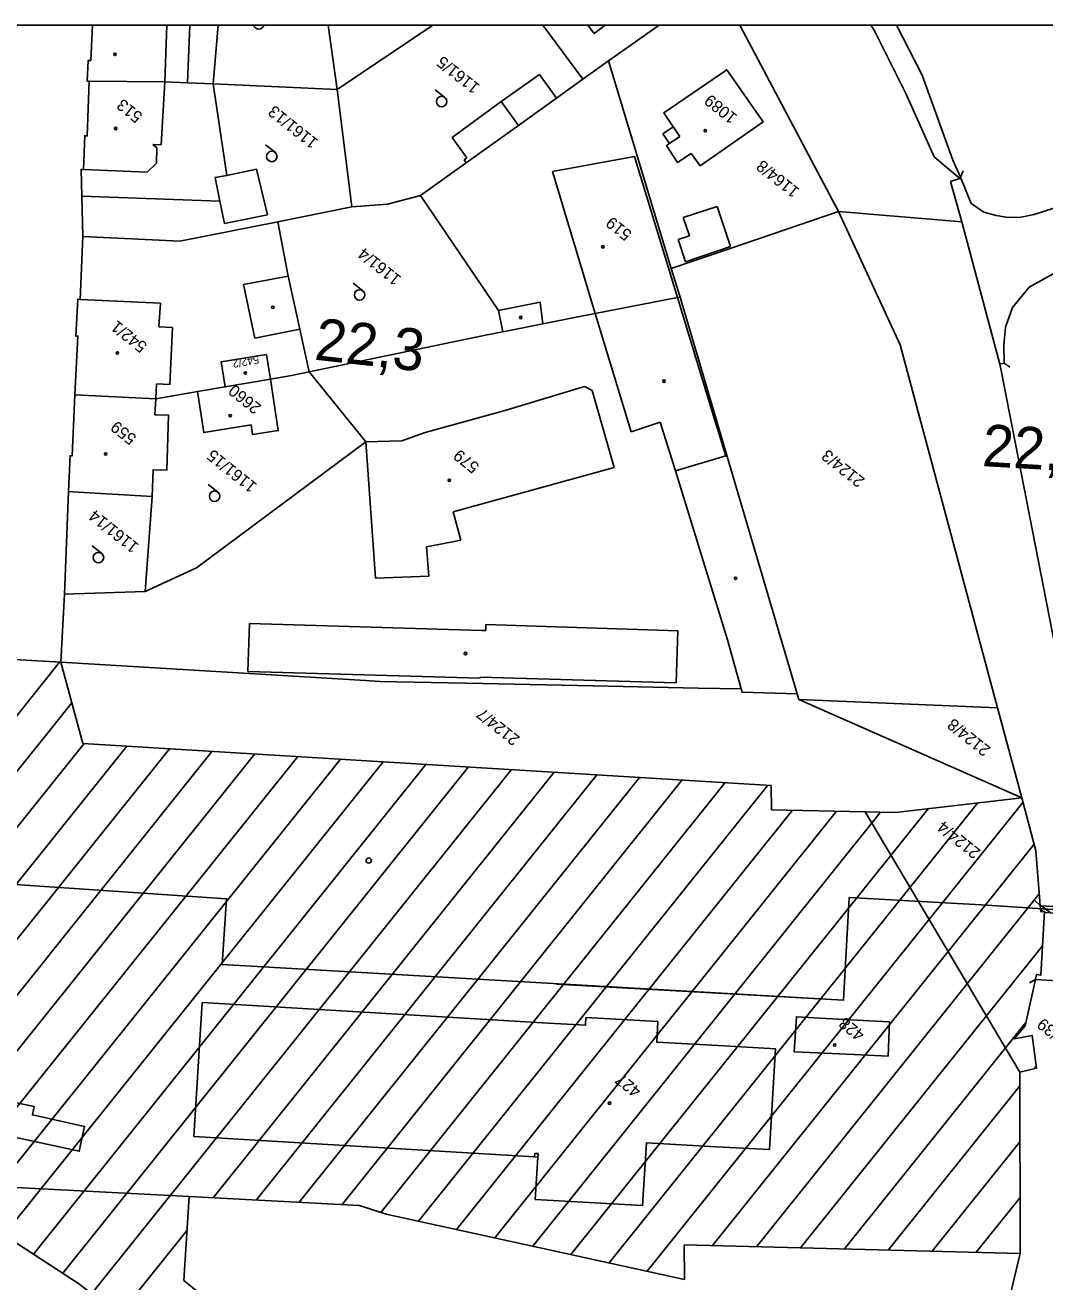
# Model space of a CAD drawing. Extents: x -794765 to -785424, y -1118958 to -1108731.
# Drawn here: x -794413.8 to -794268, y -1110211 to -1110031.4 of the extents above; entities that cross this region are included whole.
import ezdxf

# ---------------------------------------------------------------- set-up
doc = ezdxf.new("R2010")
doc.units = 0
for name, color, linetype in [('Level 66', 7, 'Continuous'), ('Level 71', 7, 'Continuous'), ('Level 73', 7, 'Continuous'), ('Level 75', 7, 'Continuous'), ('Level 76', 7, 'Continuous'), ('Level 77', 7, 'Continuous'), ('Level 78', 7, 'Continuous'), ('Level 79', 7, 'Continuous'), ('Vrstva 1', 7, 'Continuous'), ('Vrstva 53', 7, 'Continuous')]:
    doc.layers.add(name, color=color, linetype=linetype)

msp = doc.modelspace()

# ---------------------------------------------------------------- linework, layer by layer
at = {"layer": 'Level 66'}
for p, q in [((-794379.69, -1110031.45), (-794381.14, -1110031.45)), ((-794353.81, -1110041.79), (-794355.18, -1110040.69)), ((-794378.09, -1110049.62), (-794379.46, -1110048.53)), ((-794365.54, -1110069.41), (-794366.91, -1110068.32)), ((-794386.27, -1110098.18), (-794387.64, -1110097.08)), ((-794402.88, -1110106.95), (-794404.24, -1110105.85))]:
    msp.add_line(p, q, dxfattribs=at)
for centre in [(-794354.28, -1110042.37), (-794378.56, -1110050.21), (-794366.01, -1110070), (-794386.74, -1110098.76), (-794403.35, -1110107.53)]:
    msp.add_circle(centre, 0.75, dxfattribs=at)
msp.add_arc((-794380.42, -1110031.26), 0.75, 194.2282, 345.7718, dxfattribs=at)
at = {"layer": 'Level 71'}
msp.add_lwpolyline([(-793908.08, -1110031.45), (-794753.93, -1110031.45), (-794753.93, -1110332.22), (-793908.08, -1110332.22)], dxfattribs=at)
at = {"layer": 'Level 75'}
for p, q in [((-794369.2, -1110040.63), (-794370.5, -1110031.45)), ((-794355.54, -1110031.45), (-794369.2, -1110040.63)), ((-794339.81, -1110031.45), (-794334.08, -1110039.18)), ((-794330.44, -1110036.57), (-794323.16, -1110031.45)), ((-794297.55, -1110058.07), (-794311.65, -1110031.45)), ((-794330.44, -1110036.57), (-794334.08, -1110039.18)), ((-794321.44, -1110066.22), (-794330.44, -1110036.57)), ((-794386.94, -1110039.84), (-794369.2, -1110040.63)), ((-794369.2, -1110040.63), (-794367.14, -1110057.43)), ((-794405.74, -1110055.87), (-794405.6, -1110061.66)), ((-794367.14, -1110057.43), (-794377.69, -1110059.53)), ((-794297.55, -1110058.07), (-794279.9, -1110059.55)), ((-794320.19, -1110070.31), (-794321.44, -1110066.22)), ((-794320.55, -1110070.38), (-794320.19, -1110070.31)), ((-794303.46, -1110126.98), (-794320.19, -1110070.31)), ((-794378.77, -1110082.02), (-794385.24, -1110083.14)), ((-794395.15, -1110084.85), (-794406.74, -1110084.28)), ((-794389.18, -1110083.82), (-794395.15, -1110084.85)), ((-794385.24, -1110083.14), (-794389.18, -1110083.82)), ((-794407.63, -1110098.1), (-794408.19, -1110112.76)), ((-794396.66, -1110112.37), (-794395.65, -1110098.78)), ((-794408.19, -1110112.76), (-794408.75, -1110122.48)), ((-794396.66, -1110112.37), (-794408.19, -1110112.76)), ((-794422.56, -1110121.68), (-794408.75, -1110122.48)), ((-794348.44, -1110125.52), (-794332.63, -1110125.86)), ((-794303.46, -1110126.98), (-794303.22, -1110127.81)), ((-794271.33, -1110141.88), (-794303.22, -1110127.81)), ((-794303.22, -1110127.81), (-794274.78, -1110128.99)), ((-794274.78, -1110128.99), (-794271.33, -1110141.88)), ((-794271.6, -1110181.08), (-794293.7, -1110143.85)), ((-794268.74, -1110156.6), (-794268.69, -1110157.27)), ((-794271.6, -1110181.08), (-794271.56, -1110206.95)), ((-794390.37, -1110198.84), (-794428.36, -1110196.87)), ((-794273.88, -1110216.57), (-794271.56, -1110206.95))]:
    msp.add_line(p, q, dxfattribs=at)
for points in [[(-794404.2, -1110031.45), (-794404.46, -1110036.5), (-794404.81, -1110036.48), (-794404.97, -1110039.45), (-794404.67, -1110039.46)], [(-794386.94, -1110039.84), (-794386.21, -1110031.45)], [(-794292.87, -1110031.45), (-794292.31, -1110032.43), (-794287.87, -1110041.31), (-794283.86, -1110050.27), (-794280.16, -1110053.34)], [(-794281.19, -1110050.73), (-794285.58, -1110038.6), (-794289.25, -1110031.45)], [(-794321.15, -1110045.97), (-794322.63, -1110046.98), (-794321.7, -1110048.36), (-794322.11, -1110048.65), (-794320.53, -1110051.06), (-794318.62, -1110049.8), (-794317.32, -1110051.54), (-794308.31, -1110045.27), (-794313.5, -1110037.83), (-794322.51, -1110043.98), (-794321.15, -1110045.97)], [(-794404.67, -1110039.46), (-794404.96, -1110047.27), (-794405.3, -1110047.25), (-794405.48, -1110052.06), (-794405.83, -1110052.07), (-794405.74, -1110055.87)], [(-794386.94, -1110039.84), (-794390.62, -1110039.68), (-794393.88, -1110039.53), (-794404.67, -1110039.46)], [(-794334.08, -1110039.18), (-794337.86, -1110041.89), (-794343.31, -1110045.79), (-794350.75, -1110051.11), (-794357.28, -1110055.78)], [(-794405.74, -1110055.87), (-794385.99, -1110056.58), (-794386.67, -1110053.24), (-794384.99, -1110052.91), (-794386.94, -1110039.84)], [(-794280.16, -1110053.34), (-794280.09, -1110053.19), (-794281.19, -1110050.73)], [(-794279.9, -1110059.55), (-794281.51, -1110053.8), (-794280.16, -1110053.34)], [(-794357.28, -1110055.78), (-794362.01, -1110057.01), (-794367.14, -1110057.43)], [(-794357.28, -1110055.78), (-794346.16, -1110072.21), (-794345.52, -1110075.26)], [(-794405.6, -1110061.66), (-794391.71, -1110062.3), (-794377.69, -1110059.53)], [(-794377.69, -1110059.53), (-794376.2, -1110067.3), (-794374.55, -1110074.88), (-794374.25, -1110076.24), (-794373.22, -1110080.98)], [(-794321.44, -1110066.22), (-794312.87, -1110063.3), (-794297.55, -1110058.07)], [(-794297.55, -1110058.07), (-794288.69, -1110077.12), (-794274.78, -1110128.99)], [(-794261.4, -1110149.53), (-794262.44, -1110141.25), (-794274.27, -1110080.79), (-794274.45, -1110079.88), (-794279.9, -1110059.55)], [(-794406.74, -1110084.28), (-794406.29, -1110075.89), (-794406.6, -1110075.87), (-794406.32, -1110070.61), (-794405.97, -1110070.63), (-794405.6, -1110061.66)], [(-794345.52, -1110075.26), (-794339.79, -1110074.11), (-794335.52, -1110073.26), (-794332.32, -1110072.64), (-794320.55, -1110070.38)], [(-794345.52, -1110075.26), (-794348.01, -1110075.74), (-794373.22, -1110080.98)], [(-794385.24, -1110083.14), (-794385.79, -1110079.54), (-794379.34, -1110078.53), (-794378.77, -1110082.02)], [(-794373.22, -1110080.98), (-794365.1, -1110091.01), (-794389.32, -1110109), (-794396.66, -1110112.37)], [(-794373.22, -1110080.98), (-794375.75, -1110081.5), (-794378.77, -1110082.02)], [(-794378.77, -1110082.02), (-794377.65, -1110089.38), (-794381.32, -1110089.96), (-794381.53, -1110088.58), (-794388.29, -1110089.66), (-794389.18, -1110083.82)], [(-794406.74, -1110084.28), (-794407.13, -1110092.99), (-794407.4, -1110092.98), (-794407.63, -1110098.1)], [(-794395.65, -1110098.78), (-794395.53, -1110094.98), (-794393.58, -1110095.05), (-794393.32, -1110087.19), (-794395.28, -1110087.15), (-794395.15, -1110084.85)], [(-794407.63, -1110098.1), (-794407.05, -1110098.13), (-794395.65, -1110098.78)], [(-794293.7, -1110143.85), (-794307.1, -1110143.57), (-794307.17, -1110140.09), (-794405.58, -1110134.08), (-794408.75, -1110122.48)], [(-794408.75, -1110122.48), (-794365.17, -1110125.09), (-794363.1, -1110125.22), (-794348.44, -1110125.52)], [(-794332.63, -1110125.86), (-794317.58, -1110126.18), (-794311.44, -1110126.3), (-794311.31, -1110126.78), (-794303.46, -1110126.98)], [(-794271.33, -1110141.88), (-794289.38, -1110143.95), (-794293.7, -1110143.85)], [(-794271.33, -1110141.88), (-794269.31, -1110149.44), (-794268.74, -1110156.6)], [(-794268.69, -1110157.27), (-794268.62, -1110158.14), (-794268.07, -1110158.09), (-794268.62, -1110167.2), (-794269.21, -1110167.08), (-794269.37, -1110167.8), (-794270.85, -1110174.46), (-794272.42, -1110176.29), (-794269.82, -1110175.83), (-794269.24, -1110180.49), (-794271.6, -1110181.08)], [(-794339.86, -1110174.03), (-794388.53, -1110171.12), (-794389.71, -1110190.27), (-794340.99, -1110193.16), (-794340.51, -1110193.18), (-794340.89, -1110199.24), (-794325.58, -1110200.13), (-794324.99, -1110191.16), (-794315.04, -1110191.73), (-794307.41, -1110192.1), (-794306.56, -1110177.7), (-794313.89, -1110177.3), (-794323.53, -1110176.77), (-794323.37, -1110173.82), (-794333.64, -1110173.25), (-794333.69, -1110174.36), (-794339.86, -1110174.03)], [(-794293.08, -1110173.71), (-794299.28, -1110173.37), (-794303.55, -1110173.13), (-794303.85, -1110178.14), (-794299.5, -1110178.35), (-794293.27, -1110178.64), (-794290.45, -1110178.77), (-794290.22, -1110173.88), (-794293.08, -1110173.71)], [(-794417.07, -1110184.7), (-794417.13, -1110184.99), (-794419.55, -1110184.48), (-794419.48, -1110184.18), (-794421.06, -1110183.85), (-794421.13, -1110184.14), (-794425.86, -1110183.12), (-794426.05, -1110184.01), (-794426.54, -1110183.92), (-794427.16, -1110186.87), (-794426.66, -1110186.97), (-794426.85, -1110187.89), (-794413.57, -1110190.75), (-794406.09, -1110192.36), (-794405.33, -1110188.82), (-794412.8, -1110187.16), (-794412.54, -1110185.98), (-794415.55, -1110185.33), (-794415.48, -1110185.04), (-794417.07, -1110184.7)], [(-794428.36, -1110196.87), (-794423.27, -1110200.17), (-794406.05, -1110211.34), (-794389.99, -1110224.23), (-794378.62, -1110237.74), (-794363.01, -1110253.46)], [(-794390.37, -1110198.84), (-794391.12, -1110210.82), (-794349.63, -1110244.34)], [(-794271.56, -1110206.95), (-794319.59, -1110205.74), (-794319.55, -1110210.68), (-794347.4, -1110204.58), (-794362.22, -1110201.34), (-794366, -1110200.1), (-794390.37, -1110198.84)]]:
    msp.add_lwpolyline(points, dxfattribs=at)
at = {"layer": 'Level 77'}
for p, q in [((-794393.88, -1110039.53), (-794393.55, -1110031.45)), ((-794390.62, -1110039.68), (-794390.3, -1110031.45)), ((-794332.49, -1110032.65), (-794333.35, -1110031.45)), ((-794330.88, -1110031.45), (-794332.49, -1110032.65)), ((-794393.88, -1110039.53), (-794394.36, -1110048.57)), ((-794340.29, -1110038.49), (-794345.75, -1110042.38)), ((-794340.29, -1110038.49), (-794337.86, -1110041.89)), ((-794352.76, -1110047.49), (-794345.75, -1110042.38)), ((-794343.31, -1110045.79), (-794345.75, -1110042.38)), ((-794320.21, -1110047.35), (-794321.15, -1110045.97)), ((-794395.57, -1110048.5), (-794394.98, -1110048.99)), ((-794394.36, -1110048.57), (-794395.57, -1110048.5)), ((-794350.67, -1110050.41), (-794352.76, -1110047.49)), ((-794320.21, -1110047.35), (-794321.7, -1110048.36)), ((-794394.98, -1110048.99), (-794395.05, -1110051.17)), ((-794351.05, -1110050.68), (-794350.67, -1110050.41)), ((-794338.42, -1110052.38), (-794326.7, -1110050.21)), ((-794326.7, -1110050.21), (-794320.55, -1110070.38)), ((-794396.4, -1110052.48), (-794405.48, -1110052.06)), ((-794395.05, -1110051.17), (-794396.4, -1110052.48)), ((-794384.99, -1110052.91), (-794380.76, -1110052.04)), ((-794380.76, -1110052.04), (-794379.16, -1110058.57)), ((-794350.75, -1110051.11), (-794351.05, -1110050.68)), ((-794332.32, -1110072.64), (-794338.42, -1110052.38)), ((-794279.72, -1110052.26), (-794280.09, -1110053.19)), ((-794278.54, -1110056.92), (-794280.09, -1110053.19)), ((-794259.1, -1110055.12), (-794269.53, -1110058.49)), ((-794385.33, -1110059.8), (-794385.99, -1110056.58)), ((-794319.73, -1110058.95), (-794314.9, -1110057.35)), ((-794314.9, -1110057.35), (-794312.95, -1110063.07)), ((-794276.73, -1110058.17), (-794278.54, -1110056.92)), ((-794379.16, -1110058.57), (-794385.33, -1110059.8)), ((-794318.84, -1110061.55), (-794319.73, -1110058.95)), ((-794275, -1110058.64), (-794276.73, -1110058.17)), ((-794273.29, -1110058.93), (-794275, -1110058.64)), ((-794271.42, -1110058.88), (-794273.29, -1110058.93)), ((-794269.53, -1110058.49), (-794271.42, -1110058.88)), ((-794320.48, -1110062.1), (-794318.84, -1110061.55)), ((-794319.4, -1110065.27), (-794320.48, -1110062.1)), ((-794312.95, -1110063.07), (-794319.4, -1110065.27)), ((-794382.61, -1110068.52), (-794376.2, -1110067.3)), ((-794380.99, -1110076.16), (-794382.61, -1110068.52)), ((-794270.28, -1110068.87), (-794266.86, -1110067)), ((-794272.65, -1110071.78), (-794270.28, -1110068.87)), ((-794394.5, -1110071.17), (-794405.97, -1110070.63)), ((-794394.72, -1110074.56), (-794394.5, -1110071.17)), ((-794340.2, -1110071.05), (-794346.16, -1110072.21)), ((-794339.79, -1110074.11), (-794340.2, -1110071.05)), ((-794320.55, -1110070.38), (-794315.79, -1110086.05)), ((-794273.67, -1110074.59), (-794272.65, -1110071.78)), ((-794332.32, -1110072.64), (-794327.18, -1110089.55)), ((-794392.78, -1110074.65), (-794394.72, -1110074.56)), ((-794393.14, -1110082.8), (-794392.78, -1110074.65)), ((-794374.55, -1110074.88), (-794380.99, -1110076.16)), ((-794273.9, -1110077.17), (-794273.67, -1110074.59)), ((-794273.84, -1110079.76), (-794273.9, -1110077.17)), ((-794274.45, -1110079.88), (-794273.84, -1110079.76)), ((-794273.02, -1110080.33), (-794273.84, -1110079.76)), ((-794395.15, -1110084.85), (-794395.05, -1110082.71)), ((-794395.05, -1110082.71), (-794393.14, -1110082.8)), ((-794345.37, -1110086.56), (-794333.84, -1110083.06)), ((-794333.84, -1110083.06), (-794332.75, -1110083.65)), ((-794332.75, -1110083.65), (-794329.59, -1110094.66)), ((-794315.79, -1110086.05), (-794313.66, -1110093)), ((-794356.62, -1110089.66), (-794345.37, -1110086.56)), ((-794327.18, -1110089.55), (-794323.01, -1110088.19)), ((-794323.01, -1110088.19), (-794320.84, -1110095.12)), ((-794359.97, -1110090.84), (-794356.62, -1110089.66)), ((-794365.1, -1110091.01), (-794359.97, -1110090.84)), ((-794363.72, -1110110.47), (-794365.1, -1110091.01)), ((-794313.66, -1110093), (-794320.84, -1110095.12)), ((-794329.59, -1110094.66), (-794349.35, -1110100.08)), ((-794320.84, -1110095.12), (-794313.41, -1110119.27)), ((-794349.35, -1110100.08), (-794352.64, -1110100.98)), ((-794352.64, -1110100.98), (-794351.52, -1110105.04)), ((-794354.7, -1110105.65), (-794356.43, -1110105.99)), ((-794356.43, -1110105.99), (-794356.12, -1110110.17)), ((-794351.52, -1110105.04), (-794354.7, -1110105.65)), ((-794356.12, -1110110.17), (-794363.72, -1110110.47)), ((-794381.97, -1110123.81), (-794381.76, -1110116.94)), ((-794381.76, -1110116.94), (-794348.52, -1110117.95)), ((-794348.52, -1110117.95), (-794347.97, -1110117.96)), ((-794347.97, -1110117.96), (-794347.94, -1110117.11)), ((-794347.94, -1110117.11), (-794320.52, -1110118)), ((-794320.52, -1110118), (-794320.72, -1110125.44)), ((-794313.41, -1110119.27), (-794311.44, -1110126.3)), ((-794348.75, -1110124.77), (-794381.97, -1110123.81)), ((-794320.72, -1110125.44), (-794348.75, -1110124.62)), ((-794348.75, -1110124.62), (-794348.75, -1110124.77)), ((-794269.4, -1110156.56), (-794268.69, -1110157.26)), ((-794268.69, -1110157.27), (-794260.56, -1110157.72)), ((-794270.24, -1110168.31), (-794269.37, -1110167.8)), ((-794269.37, -1110167.8), (-794260.45, -1110168.37)), ((-794340.95, -1110192.69), (-794340.99, -1110193.16)), ((-794340.48, -1110192.69), (-794340.95, -1110192.69)), ((-794340.51, -1110193.18), (-794340.48, -1110192.69))]:
    msp.add_line(p, q, dxfattribs=at)
at = {"layer": 'Level 78'}
for p, q in [((-794408.9, -1110122.47), (-794467.03, -1110194.96)), ((-794407.16, -1110128.29), (-794460.84, -1110195.24)), ((-794405.41, -1110134.09), (-794454.66, -1110195.53)), ((-794399.3, -1110134.47), (-794448.49, -1110195.83)), ((-794393.19, -1110134.84), (-794442.34, -1110196.15)), ((-794387.08, -1110135.21), (-794436.19, -1110196.47)), ((-794380.97, -1110135.59), (-794430.04, -1110196.79)), ((-794374.86, -1110135.96), (-794425.29, -1110198.86)), ((-794368.75, -1110136.33), (-794421.08, -1110201.6)), ((-794362.64, -1110136.7), (-794416.86, -1110204.33)), ((-794356.53, -1110137.08), (-794412.64, -1110207.06)), ((-794350.42, -1110137.45), (-794408.43, -1110209.8)), ((-794344.31, -1110137.82), (-794404.35, -1110212.71)), ((-794338.2, -1110138.19), (-794386.96, -1110199.01)), ((-794332.09, -1110138.57), (-794380.81, -1110199.33)), ((-794325.98, -1110138.94), (-794374.66, -1110199.65)), ((-794319.87, -1110139.31), (-794368.5, -1110199.97)), ((-794313.76, -1110139.69), (-794362.99, -1110201.09)), ((-794307.65, -1110140.06), (-794357.59, -1110202.35)), ((-794304.11, -1110143.63), (-794352.14, -1110203.55)), ((-794297.81, -1110143.77), (-794346.69, -1110204.74)), ((-794291.51, -1110143.9), (-794341.24, -1110205.93)), ((-794284.71, -1110143.41), (-794335.79, -1110207.13)), ((-794277.65, -1110142.61), (-794330.34, -1110208.32)), ((-794271.16, -1110142.51), (-794324.88, -1110209.51)), ((-794269.56, -1110148.5), (-794315.53, -1110205.84)), ((-794268.82, -1110155.58), (-794309.25, -1110206)), ((-794268.37, -1110163), (-794302.97, -1110206.16)), ((-794270.74, -1110173.95), (-794296.69, -1110206.32)), ((-794269.28, -1110180.13), (-794269.66, -1110180.59)), ((-794271.6, -1110183.01), (-794290.41, -1110206.48)), ((-794271.58, -1110190.99), (-794284.12, -1110206.63)), ((-794271.57, -1110198.97), (-794277.84, -1110206.79)), ((-794390.67, -1110203.64), (-794400.45, -1110215.83))]:
    msp.add_line(p, q, dxfattribs=at)
at = {"layer": 'Level 79'}
for centre in [(-794400.99, -1110035.62), (-794400.88, -1110046.22), (-794316.58, -1110046.52), (-794331.23, -1110063.12), (-794378.41, -1110071.76), (-794342.97, -1110073.22), (-794400.64, -1110078.31), (-794382.34, -1110081.16), (-794322.48, -1110082.32), (-794384.51, -1110087.26), (-794402.33, -1110092.74), (-794353.18, -1110096.48), (-794312.25, -1110110.5), (-794350.87, -1110121.23), (-794298.07, -1110177.19), (-794330.27, -1110185.49)]:
    msp.add_circle(centre, 0.175, dxfattribs=at)
at = {"layer": 'Vrstva 1'}
for p, q in [((-794296.81, -1110170.78), (-794296, -1110156.1)), ((-794296, -1110156.1), (-794276.26, -1110157.18)), ((-794276.26, -1110157.18), (-794261.61, -1110158.14)), ((-794268.62, -1110158.14), (-794268.69, -1110157.27)), ((-794268.26, -1110158.11), (-794268.65, -1110157.8)), ((-794268.07, -1110158.09), (-794268.62, -1110158.14)), ((-794267.24, -1110158.29), (-794268.5, -1110157.28)), ((-794268.08, -1110158.24), (-794248.27, -1110159.4)), ((-794337.85, -1110168.5), (-794296.81, -1110170.78))]:
    msp.add_line(p, q, dxfattribs=at)
msp.add_lwpolyline([(-794434.97, -1110152.89), (-794385.02, -1110156.28), (-794385.66, -1110165.69), (-794296.81, -1110170.78), (-794296, -1110156.1)], dxfattribs=at)
msp.add_lwpolyline([(-794268.08, -1110158.24), (-794268.07, -1110158.09), (-794268.62, -1110158.14), (-794268.69, -1110157.27), (-794260.18, -1110157.74), (-794247.55, -1110158.45), (-794247.7, -1110159.29), (-794248.25, -1110159.19), (-794248.27, -1110159.4)], close=True, dxfattribs=at)
msp.add_circle((-794364.7, -1110150.82), 0.375, dxfattribs=at)
at = {"layer": 'Vrstva 53'}
for points in [[(-794595.3, -1110111.99), (-794574.38, -1110113.1), (-794572.49, -1110113.2), (-794561.85, -1110113.73), (-794561.78, -1110112.27), (-794541.76, -1110113.39), (-794541.84, -1110114.79), (-794530.75, -1110115.42), (-794430.53, -1110121.22), (-794408.75, -1110122.48), (-794405.58, -1110134.08)], [(-794405.58, -1110134.08), (-794307.17, -1110140.09), (-794307.1, -1110143.57), (-794293.7, -1110143.85), (-794289.38, -1110143.95), (-794271.33, -1110141.88), (-794269.31, -1110149.44), (-794268.74, -1110156.6), (-794268.69, -1110157.27), (-794268.62, -1110158.14), (-794268.07, -1110158.09), (-794268.62, -1110167.2), (-794269.21, -1110167.08), (-794269.37, -1110167.8), (-794270.85, -1110174.46), (-794272.42, -1110176.29), (-794269.82, -1110175.83), (-794269.24, -1110180.49), (-794271.6, -1110181.08), (-794271.56, -1110206.95), (-794319.59, -1110205.74), (-794319.55, -1110210.68), (-794347.4, -1110204.58)], [(-794347.4, -1110204.58), (-794362.22, -1110201.34), (-794366, -1110200.1), (-794390.37, -1110198.84), (-794391.12, -1110210.82), (-794349.63, -1110244.34), (-794352.48, -1110246.49), (-794363.01, -1110253.46), (-794378.62, -1110237.74), (-794389.99, -1110224.23), (-794406.05, -1110211.34), (-794428.36, -1110196.87)]]:
    msp.add_lwpolyline(points, dxfattribs=at)

# ---------------------------------------------------------------- texts
at = {"layer": 'Level 73'}
for s, rotation, p in [('22,3', 353.6064, (-794372.6, -1110079.23)), ('22,4', 356.64, (-794277.08, -1110094.45))]:
    msp.add_text(s, height=6, rotation=rotation, dxfattribs=at).set_placement(p)
at = {"layer": 'Level 76'}
for s, height, rotation, p in [('1161/5', 1.7, 141.279, (-794348.68, -1110040.09)), ('1089', 1.7, 141.279, (-794311.89, -1110044.39)), ('513', 1.7, 141.279, (-794396.91, -1110044.24)), ('1161/13', 1.7, 141.279, (-794371.8, -1110047.95)), ('1164/8', 1.7, 141.279, (-794302.97, -1110054.95)), ('519', 1.7, 141.279, (-794326.95, -1110061.07)), ('1161/4', 1.7, 141.279, (-794359.94, -1110067.48)), ('542/1', 1.7, 141.279, (-794396.26, -1110077.08)), ('542/2', 1.139, 190.279, (-794380.5, -1110078.63)), ('2660', 1.7, 141.279, (-794379.94, -1110085.85)), ('559', 1.7, 141.279, (-794397.77, -1110090.25)), ('1161/15', 1.7, 141.279, (-794380.55, -1110097.1)), ('579', 1.7, 141.279, (-794348.76, -1110094.32)), ('2124/3', 1.7, 141.279, (-794293.65, -1110096.33)), ('1161/14', 1.7, 141.279, (-794397.44, -1110105.72)), ('2124/7', 1.7, 141.279, (-794342.98, -1110133.23)), ('2124/8', 1.7, 141.279, (-794275.67, -1110134.75)), ('2124/4', 1.7, 141.279, (-794277.09, -1110149.4)), ('428', 1.7, 141.279, (-794293.65, -1110175.45)), ('2083/39', 1.7, 141.279, (-794261.84, -1110178.36)), ('427', 1.7, 141.279, (-794325.61, -1110183.51))]:
    msp.add_text(s, height=height, rotation=rotation, dxfattribs=at).set_placement(p)

doc.saveas('drawing.dxf')
